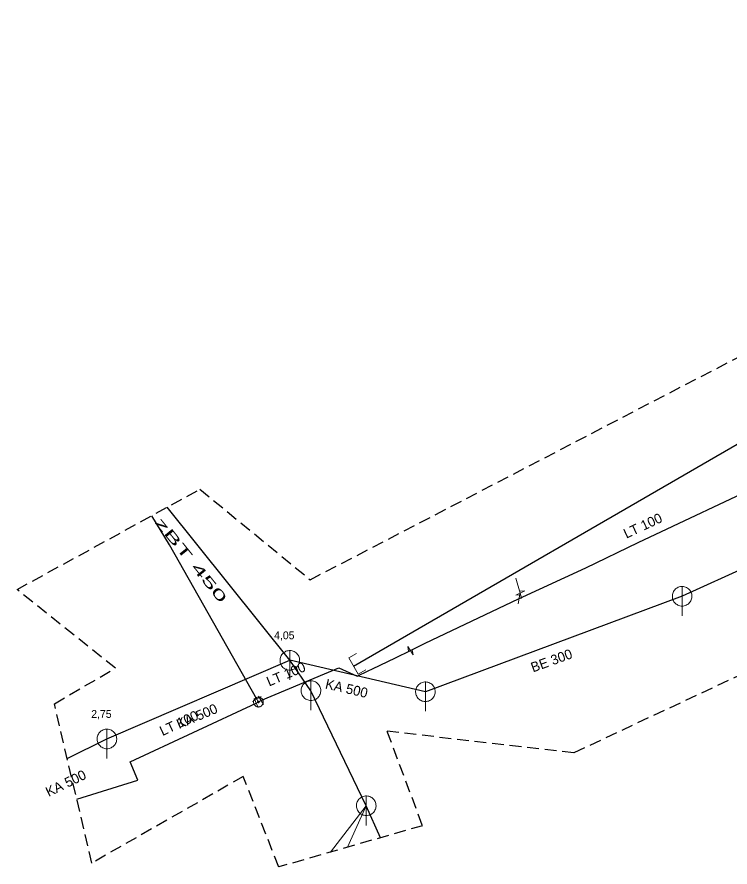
# Model space of a CAD drawing. Extents: x -688693 to -688474, y -974081 to -973994.
# Drawn here: x -688692.9 to -688620.1, y -974081 to -973994.2 of the extents above; entities that cross this region are included whole.
import ezdxf

# ---------------------------------------------------------------- set-up
doc = ezdxf.new("R2010")
doc.units = 0
doc.header["$LTSCALE"] = 0.4
doc.linetypes.add('MEDIUM_DASHED', pattern=[4.5, 3, -1.5])
for name, color, linetype, lineweight in [('1', 7, 'MEDIUM_DASHED', 25), ('11', 7, 'Continuous', 13), ('13', 7, 'Continuous', 13), ('14', 7, 'Continuous', 25), ('17', 7, 'Continuous', 25), ('22', 7, 'Continuous', 13), ('31', 7, 'Continuous', 13), ('34', 7, 'Continuous', 13), ('47', 7, 'Continuous', 13)]:
    doc.layers.add(name, color=color, linetype=linetype, lineweight=lineweight)

msp = doc.modelspace()

# ---------------------------------------------------------------- linework, layer by layer
at = {"layer": '1'}
msp.add_lwpolyline([(-688692.931, -974052.713), (-688674.241, -974042.463), (-688662.987, -974051.708), (-688552.455, -973994.231), (-688543.813, -974004.28), (-688496.988, -974010.309), (-688488.949, -974009.103), (-688474.077, -974014.529), (-688476.69, -974033.621), (-688494.978, -974032.616), (-688541.804, -974022.367), (-688555.67, -974019.352), (-688572.552, -974027.19), (-688578.982, -974032.415), (-688581.193, -974043.669), (-688636.057, -974069.393), (-688655.149, -974067.182), (-688651.532, -974076.829), (-688666.202, -974081.049), (-688669.82, -974071.805), (-688685.294, -974080.647), (-688689.113, -974064.369), (-688682.883, -974060.751)], close=True, dxfattribs=at)
at = {"layer": '11'}
for p in [(-688660.897, -974079.523), (-688659.187, -974079.031)]:
    msp.add_line(p, (-688657.26, -974074.794), dxfattribs=at)
at = {"layer": '13'}
msp.add_line((-688641.537, -974053.074), (-688641.977, -974051.563), dxfattribs=at)
msp.add_lwpolyline([(-688641.666, -974053.675), (-688641.397, -974053.585), (-688641.537, -974053.074)], dxfattribs=at)
at = {"layer": '14'}
for p, q in [((-688658.556, -974060.52), (-688598.575, -974025.813)), ((-688596.688, -974040.453), (-688625, -974053.399)), ((-688665.07, -974059.94), (-688677.608, -974044.31)), ((-688625, -974053.399), (-688651.219, -974063.149)), ((-688683.75, -974067.969), (-688665.07, -974059.94)), ((-688651.219, -974063.149), (-688665.07, -974059.94)), ((-688662.91, -974063.039), (-688665.07, -974059.94)), ((-688657.26, -974074.794), (-688662.91, -974063.039)), ((-688687.801, -974069.961), (-688683.75, -974067.969)), ((-688655.817, -974078.062), (-688657.26, -974074.794))]:
    msp.add_line(p, q, dxfattribs=at)
at = {"layer": '14', "lineweight": 13}
for p, q in [((-688641.695, -974053.653), (-688641.666, -974053.675)), ((-688668.28, -974064.199), (-688668.449, -974063.89)), ((-688668.28, -974064.199), (-688668.02, -974064.039)), ((-688668.51, -974064.3), (-688668.28, -974064.199))]:
    msp.add_line(p, q, dxfattribs=at)
at = {"layer": '17'}
for points in [[(-688652.752, -974058.945), (-688651.228, -974058.19), (-688641.695, -974053.653), (-688634.831, -974050.489), (-688629.499, -974047.91), (-688602.322, -974035.098)], [(-688668.449, -974063.89), (-688677.359, -974048.149), (-688679.177, -974045.17)], [(-688668.02, -974064.039), (-688660.05, -974060.699), (-688658.199, -974061.559), (-688657.05, -974061.01), (-688656.609, -974060.809), (-688654.27, -974059.68), (-688652.752, -974058.945)], [(-688686.828, -974074.107), (-688680.6, -974072.17), (-688681.36, -974070.309), (-688668.51, -974064.3)]]:
    msp.add_lwpolyline(points, dxfattribs=at)
at = {"layer": '22'}
for p, q in [((-688625, -974055.399), (-688624.999, -974052.399)), ((-688665.07, -974061.94), (-688665.069, -974058.94)), ((-688662.91, -974065.04), (-688662.909, -974062.04)), ((-688651.219, -974065.149), (-688651.218, -974062.149)), ((-688683.75, -974069.969), (-688683.749, -974066.969)), ((-688657.26, -974076.794), (-688657.259, -974073.794))]:
    msp.add_line(p, q, dxfattribs=at)
for points in [[(-688624, -974053.399), (-688624.005, -974053.29), (-688624.023, -974053.182), (-688624.053, -974053.076), (-688624.093, -974052.975), (-688624.145, -974052.878), (-688624.207, -974052.788), (-688624.279, -974052.705), (-688624.359, -974052.631), (-688624.447, -974052.565), (-688624.541, -974052.51), (-688624.641, -974052.465), (-688624.746, -974052.432), (-688624.853, -974052.41), (-688624.962, -974052.4), (-688625.072, -974052.402), (-688625.18, -974052.416), (-688625.287, -974052.441), (-688625.39, -974052.478), (-688625.488, -974052.527), (-688625.58, -974052.585), (-688625.666, -974052.654), (-688625.743, -974052.731), (-688625.812, -974052.817), (-688625.871, -974052.909), (-688625.919, -974053.007), (-688625.956, -974053.11), (-688625.982, -974053.217), (-688625.996, -974053.325), (-688625.999, -974053.435), (-688625.989, -974053.544), (-688625.968, -974053.651), (-688625.934, -974053.755), (-688625.89, -974053.855), (-688625.835, -974053.95), (-688625.769, -974054.038), (-688625.695, -974054.118), (-688625.612, -974054.19), (-688625.522, -974054.252), (-688625.426, -974054.304), (-688625.324, -974054.345), (-688625.219, -974054.375), (-688625.111, -974054.393), (-688625.001, -974054.399), (-688624.892, -974054.393), (-688624.784, -974054.375), (-688624.679, -974054.346), (-688624.577, -974054.305), (-688624.48, -974054.253), (-688624.39, -974054.191), (-688624.307, -974054.12), (-688624.232, -974054.04), (-688624.167, -974053.952), (-688624.111, -974053.858), (-688624.067, -974053.758), (-688624.033, -974053.654), (-688624.011, -974053.546), (-688624.001, -974053.437)], [(-688664.07, -974059.94), (-688664.075, -974059.831), (-688664.093, -974059.723), (-688664.123, -974059.617), (-688664.163, -974059.516), (-688664.215, -974059.419), (-688664.277, -974059.329), (-688664.349, -974059.246), (-688664.429, -974059.172), (-688664.517, -974059.106), (-688664.611, -974059.051), (-688664.711, -974059.006), (-688664.816, -974058.973), (-688664.923, -974058.951), (-688665.032, -974058.941), (-688665.142, -974058.943), (-688665.25, -974058.957), (-688665.357, -974058.982), (-688665.46, -974059.019), (-688665.558, -974059.068), (-688665.65, -974059.126), (-688665.736, -974059.195), (-688665.813, -974059.272), (-688665.882, -974059.358), (-688665.941, -974059.45), (-688665.989, -974059.548), (-688666.026, -974059.651), (-688666.052, -974059.758), (-688666.066, -974059.866), (-688666.069, -974059.976), (-688666.059, -974060.085), (-688666.038, -974060.192), (-688666.004, -974060.296), (-688665.96, -974060.396), (-688665.905, -974060.491), (-688665.839, -974060.579), (-688665.765, -974060.659), (-688665.682, -974060.731), (-688665.592, -974060.793), (-688665.496, -974060.845), (-688665.394, -974060.886), (-688665.289, -974060.916), (-688665.181, -974060.934), (-688665.071, -974060.94), (-688664.962, -974060.934), (-688664.854, -974060.916), (-688664.749, -974060.887), (-688664.647, -974060.846), (-688664.55, -974060.794), (-688664.46, -974060.732), (-688664.377, -974060.661), (-688664.302, -974060.581), (-688664.237, -974060.493), (-688664.181, -974060.399), (-688664.137, -974060.299), (-688664.103, -974060.195), (-688664.081, -974060.087), (-688664.071, -974059.978)], [(-688661.91, -974063.04), (-688661.915, -974062.931), (-688661.933, -974062.823), (-688661.963, -974062.717), (-688662.003, -974062.616), (-688662.055, -974062.519), (-688662.117, -974062.429), (-688662.189, -974062.346), (-688662.269, -974062.272), (-688662.357, -974062.206), (-688662.451, -974062.151), (-688662.551, -974062.106), (-688662.656, -974062.073), (-688662.763, -974062.051), (-688662.872, -974062.041), (-688662.982, -974062.043), (-688663.09, -974062.057), (-688663.197, -974062.082), (-688663.3, -974062.119), (-688663.398, -974062.168), (-688663.49, -974062.226), (-688663.576, -974062.295), (-688663.653, -974062.372), (-688663.722, -974062.458), (-688663.781, -974062.55), (-688663.829, -974062.648), (-688663.866, -974062.751), (-688663.892, -974062.858), (-688663.906, -974062.966), (-688663.909, -974063.076), (-688663.899, -974063.185), (-688663.878, -974063.292), (-688663.844, -974063.396), (-688663.8, -974063.496), (-688663.745, -974063.591), (-688663.679, -974063.679), (-688663.605, -974063.759), (-688663.522, -974063.831), (-688663.432, -974063.893), (-688663.336, -974063.945), (-688663.234, -974063.986), (-688663.129, -974064.016), (-688663.021, -974064.034), (-688662.911, -974064.04), (-688662.802, -974064.034), (-688662.694, -974064.016), (-688662.589, -974063.987), (-688662.487, -974063.946), (-688662.39, -974063.894), (-688662.3, -974063.832), (-688662.217, -974063.761), (-688662.142, -974063.681), (-688662.077, -974063.593), (-688662.021, -974063.499), (-688661.977, -974063.399), (-688661.943, -974063.295), (-688661.921, -974063.187), (-688661.911, -974063.078)], [(-688650.219, -974063.149), (-688650.224, -974063.04), (-688650.242, -974062.932), (-688650.272, -974062.826), (-688650.312, -974062.725), (-688650.364, -974062.628), (-688650.426, -974062.538), (-688650.498, -974062.455), (-688650.578, -974062.381), (-688650.666, -974062.315), (-688650.76, -974062.26), (-688650.86, -974062.215), (-688650.965, -974062.182), (-688651.072, -974062.16), (-688651.181, -974062.15), (-688651.291, -974062.152), (-688651.399, -974062.166), (-688651.506, -974062.191), (-688651.609, -974062.228), (-688651.707, -974062.277), (-688651.799, -974062.335), (-688651.885, -974062.404), (-688651.962, -974062.481), (-688652.031, -974062.567), (-688652.09, -974062.659), (-688652.138, -974062.757), (-688652.175, -974062.86), (-688652.201, -974062.967), (-688652.215, -974063.075), (-688652.218, -974063.185), (-688652.208, -974063.294), (-688652.187, -974063.401), (-688652.153, -974063.505), (-688652.109, -974063.605), (-688652.054, -974063.7), (-688651.988, -974063.788), (-688651.914, -974063.868), (-688651.831, -974063.94), (-688651.741, -974064.002), (-688651.645, -974064.054), (-688651.543, -974064.095), (-688651.438, -974064.125), (-688651.33, -974064.143), (-688651.22, -974064.149), (-688651.111, -974064.143), (-688651.003, -974064.125), (-688650.898, -974064.096), (-688650.796, -974064.055), (-688650.699, -974064.003), (-688650.609, -974063.941), (-688650.526, -974063.87), (-688650.451, -974063.79), (-688650.386, -974063.702), (-688650.33, -974063.608), (-688650.286, -974063.508), (-688650.252, -974063.404), (-688650.23, -974063.296), (-688650.22, -974063.187)], [(-688682.75, -974067.969), (-688682.755, -974067.86), (-688682.773, -974067.752), (-688682.803, -974067.646), (-688682.843, -974067.545), (-688682.895, -974067.448), (-688682.957, -974067.358), (-688683.029, -974067.275), (-688683.109, -974067.201), (-688683.197, -974067.135), (-688683.291, -974067.08), (-688683.391, -974067.035), (-688683.496, -974067.002), (-688683.603, -974066.98), (-688683.712, -974066.97), (-688683.822, -974066.972), (-688683.93, -974066.986), (-688684.037, -974067.011), (-688684.14, -974067.048), (-688684.238, -974067.097), (-688684.33, -974067.155), (-688684.416, -974067.224), (-688684.493, -974067.301), (-688684.562, -974067.387), (-688684.621, -974067.479), (-688684.669, -974067.577), (-688684.706, -974067.68), (-688684.732, -974067.787), (-688684.746, -974067.895), (-688684.749, -974068.005), (-688684.739, -974068.114), (-688684.718, -974068.221), (-688684.684, -974068.325), (-688684.64, -974068.425), (-688684.585, -974068.52), (-688684.519, -974068.608), (-688684.445, -974068.688), (-688684.362, -974068.76), (-688684.272, -974068.822), (-688684.176, -974068.874), (-688684.074, -974068.915), (-688683.969, -974068.945), (-688683.861, -974068.963), (-688683.751, -974068.969), (-688683.642, -974068.963), (-688683.534, -974068.945), (-688683.429, -974068.916), (-688683.327, -974068.875), (-688683.23, -974068.823), (-688683.14, -974068.761), (-688683.057, -974068.69), (-688682.982, -974068.61), (-688682.917, -974068.522), (-688682.861, -974068.428), (-688682.817, -974068.328), (-688682.783, -974068.224), (-688682.761, -974068.116), (-688682.751, -974068.007)], [(-688656.26, -974074.794), (-688656.265, -974074.685), (-688656.283, -974074.577), (-688656.313, -974074.471), (-688656.353, -974074.37), (-688656.405, -974074.273), (-688656.467, -974074.183), (-688656.539, -974074.1), (-688656.619, -974074.026), (-688656.707, -974073.96), (-688656.801, -974073.905), (-688656.901, -974073.86), (-688657.006, -974073.827), (-688657.113, -974073.805), (-688657.222, -974073.795), (-688657.332, -974073.797), (-688657.44, -974073.811), (-688657.547, -974073.836), (-688657.65, -974073.873), (-688657.748, -974073.922), (-688657.84, -974073.98), (-688657.926, -974074.049), (-688658.003, -974074.126), (-688658.072, -974074.212), (-688658.131, -974074.304), (-688658.179, -974074.402), (-688658.216, -974074.505), (-688658.242, -974074.612), (-688658.256, -974074.72), (-688658.259, -974074.83), (-688658.249, -974074.939), (-688658.228, -974075.046), (-688658.194, -974075.15), (-688658.15, -974075.25), (-688658.095, -974075.345), (-688658.029, -974075.433), (-688657.955, -974075.513), (-688657.872, -974075.585), (-688657.782, -974075.647), (-688657.686, -974075.699), (-688657.584, -974075.74), (-688657.479, -974075.77), (-688657.371, -974075.788), (-688657.261, -974075.794), (-688657.152, -974075.788), (-688657.044, -974075.77), (-688656.939, -974075.741), (-688656.837, -974075.7), (-688656.74, -974075.648), (-688656.65, -974075.586), (-688656.567, -974075.515), (-688656.492, -974075.435), (-688656.427, -974075.347), (-688656.371, -974075.253), (-688656.327, -974075.153), (-688656.293, -974075.049), (-688656.271, -974074.941), (-688656.261, -974074.832)]]:
    msp.add_lwpolyline(points, close=True, dxfattribs=at)
at = {"layer": '31'}
msp.add_lwpolyline([(-688658.26, -974059.232), (-688659.04, -974059.684), (-688658.072, -974061.356), (-688657.292, -974060.905)], dxfattribs=at)
at = {"layer": '34'}
for p, q in [((-688641.577, -974053.182), (-688641.755, -974054.166)), ((-688668.887, -974064.13), (-688668.01, -974063.65)), ((-688668.722, -974063.847), (-688668.298, -974064.753)), ((-688668.282, -974063.613), (-688667.758, -974064.465))]:
    msp.add_line(p, q, dxfattribs=at)
at = {"layer": '47'}
for p, q in [((-688641.993, -974053.3), (-688641.483, -974053.267)), ((-688653.028, -974058.517), (-688652.938, -974059.019))]:
    msp.add_line(p, q, dxfattribs=at)
for points in [[(-688641.993, -974053.3), (-688641.08, -974052.847), (-688641.59, -974052.88)], [(-688653.028, -974058.517), (-688652.475, -974059.372), (-688652.565, -974058.87)]]:
    msp.add_lwpolyline(points, dxfattribs=at)
for points in [[(-688667.821, -974063.999), (-688667.844, -974063.953), (-688667.873, -974063.908), (-688667.905, -974063.868), (-688667.941, -974063.83), (-688667.982, -974063.797), (-688668.026, -974063.768), (-688668.072, -974063.744), (-688668.121, -974063.725), (-688668.171, -974063.711), (-688668.223, -974063.702), (-688668.276, -974063.698), (-688668.328, -974063.701), (-688668.379, -974063.709), (-688668.43, -974063.722), (-688668.479, -974063.74), (-688668.525, -974063.763), (-688668.57, -974063.792), (-688668.611, -974063.825), (-688668.648, -974063.86), (-688668.681, -974063.901), (-688668.71, -974063.945), (-688668.735, -974063.992), (-688668.754, -974064.041), (-688668.768, -974064.09), (-688668.776, -974064.142), (-688668.78, -974064.195), (-688668.777, -974064.247), (-688668.769, -974064.298), (-688668.756, -974064.349), (-688668.738, -974064.398), (-688668.715, -974064.444), (-688668.686, -974064.489), (-688668.654, -974064.53), (-688668.618, -974064.567), (-688668.577, -974064.6), (-688668.534, -974064.63), (-688668.487, -974064.654), (-688668.438, -974064.673), (-688668.388, -974064.687), (-688668.336, -974064.695), (-688668.283, -974064.699), (-688668.232, -974064.697), (-688668.18, -974064.688), (-688668.129, -974064.675), (-688668.08, -974064.657), (-688668.034, -974064.634), (-688667.989, -974064.605), (-688667.948, -974064.574), (-688667.911, -974064.537), (-688667.878, -974064.496), (-688667.848, -974064.453), (-688667.825, -974064.406), (-688667.806, -974064.358), (-688667.792, -974064.307), (-688667.783, -974064.255), (-688667.779, -974064.202), (-688667.782, -974064.151), (-688667.79, -974064.099), (-688667.803, -974064.048)], [(-688668.204, -974064.166), (-688668.208, -974064.158), (-688668.213, -974064.151), (-688668.218, -974064.144), (-688668.224, -974064.138), (-688668.231, -974064.133), (-688668.238, -974064.128), (-688668.245, -974064.124), (-688668.253, -974064.121), (-688668.262, -974064.119), (-688668.27, -974064.117), (-688668.279, -974064.117), (-688668.288, -974064.117), (-688668.296, -974064.118), (-688668.304, -974064.12), (-688668.312, -974064.123), (-688668.32, -974064.127), (-688668.327, -974064.132), (-688668.334, -974064.137), (-688668.34, -974064.143), (-688668.345, -974064.15), (-688668.35, -974064.157), (-688668.354, -974064.164), (-688668.357, -974064.172), (-688668.36, -974064.181), (-688668.361, -974064.189), (-688668.361, -974064.198), (-688668.361, -974064.207), (-688668.36, -974064.215), (-688668.358, -974064.223), (-688668.355, -974064.231), (-688668.351, -974064.239), (-688668.346, -974064.246), (-688668.341, -974064.253), (-688668.335, -974064.259), (-688668.328, -974064.264), (-688668.322, -974064.269), (-688668.314, -974064.273), (-688668.306, -974064.276), (-688668.297, -974064.279), (-688668.289, -974064.28), (-688668.28, -974064.28), (-688668.271, -974064.28), (-688668.263, -974064.279), (-688668.255, -974064.277), (-688668.247, -974064.274), (-688668.239, -974064.27), (-688668.232, -974064.265), (-688668.225, -974064.26), (-688668.219, -974064.254), (-688668.214, -974064.247), (-688668.209, -974064.241), (-688668.205, -974064.233), (-688668.202, -974064.225), (-688668.2, -974064.216), (-688668.198, -974064.208), (-688668.198, -974064.199), (-688668.198, -974064.19), (-688668.199, -974064.182), (-688668.201, -974064.174)]]:
    msp.add_lwpolyline(points, close=True, dxfattribs=at)

# ---------------------------------------------------------------- texts
at = {"layer": '1'}
for s, rotation, p in [('LT 100', 25, (-688630.694, -974047.52)), ('BE 300', 20, (-688640.229, -974061.181)), ('LT 100', 23, (-688667.182, -974062.62)), ('KA 500', 347, (-688661.515, -974062.8)), ('KA 500', 23, (-688676.381, -974066.963)), ('LT 100', 25, (-688678.069, -974067.682)), ('KA 500', 26, (-688689.7, -974073.901))]:
    msp.add_text(s, height=1, rotation=rotation, dxfattribs=at).set_placement(p)
at = {"layer": '1', "width": 2.15}
msp.add_text('zBT 450 ', height=1, rotation=309, dxfattribs=at).set_placement((-688678.913, -974045.854))
at = {"layer": '1'}
for s, p in [('4,05', (-688666.67, -974057.787)), ('2,75', (-688685.35, -974065.817))]:
    msp.add_text(s, height=0.8, dxfattribs=at).set_placement(p)

doc.saveas('drawing.dxf')
